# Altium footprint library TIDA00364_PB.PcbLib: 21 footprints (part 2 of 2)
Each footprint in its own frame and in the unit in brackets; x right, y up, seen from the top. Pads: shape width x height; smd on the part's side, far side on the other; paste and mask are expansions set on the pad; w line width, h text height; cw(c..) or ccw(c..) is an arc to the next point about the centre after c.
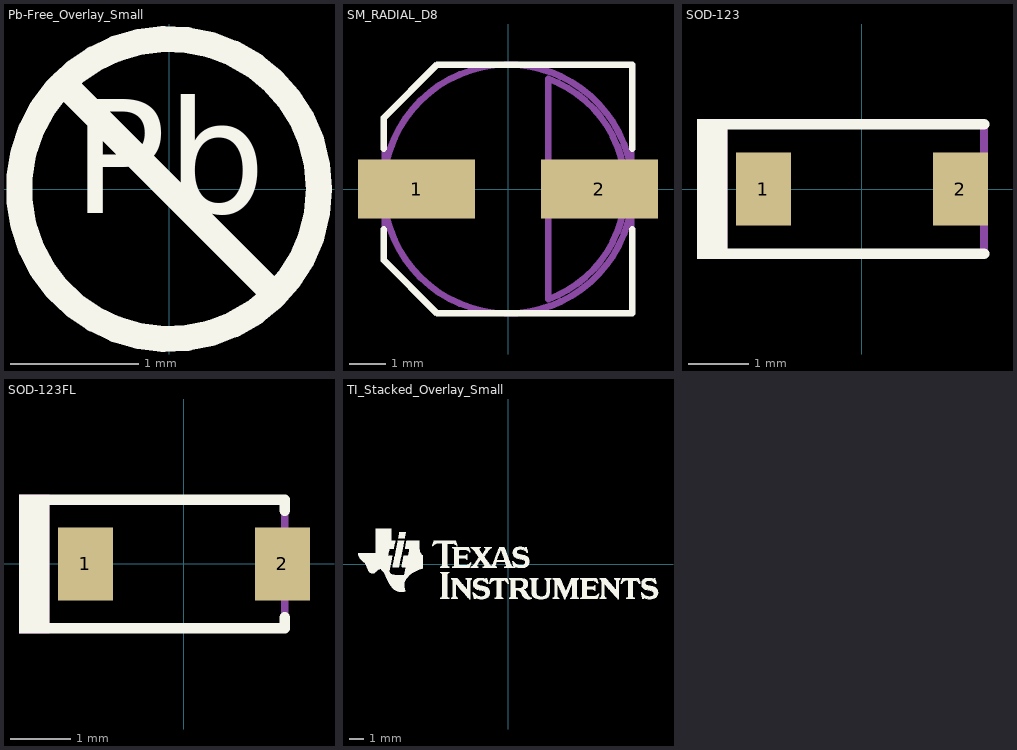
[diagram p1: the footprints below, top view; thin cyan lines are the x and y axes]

## Pb-Free_Overlay_Small [mm]
height 1.35
Top Overlay:
  circle w0.203: c0,0 r1.168
  lines w0.203: -0.826,0.826 0.826,-0.826
  text "Pb" at -0.752,-0.48 h1.52

## SM_RADIAL_D8 [mm] "6.3 x 7.7mm:  Panasonic D8"
height 8
pads (2):
  rect 3.2x1.6 smd: 1(-2.5,0) 2(2.5,0)
Top Overlay:
  lines w0.178: -3.398,-1.099 -3.398,-1.942 -1.94,-3.4 3.4,-3.4 3.4,-1.1 ; -3.398,1.099 -3.398,1.942 -1.94,3.4 3.4,3.4 3.4,1.1
Mechanical 5:
  lines w0.127: -3.398,-1.942 -1.94,-3.4 3.4,-3.4 3.4,3.4 -1.94,3.4 -3.398,1.942 -3.398,-1.942
  text ".Designator" at 0.762,0.889 h0.76
Mechanical 13:
  circle w0.178: c0,0 r3.4
  lines w0.178: 1.097,-3.014 ccw(c0,0) 1.097,3.014 1.097,-3.014
3D body: height 0.6, standoff 0, extent -3.398,-3.401 3.401,3.401
3D body: height 8.01, standoff 7.9, extent 1.097,-3.015 3.208,3.015
3D body: height 8, standoff 0.6, extent -3.399,-3.399 3.399,3.399

## SOD-123 [mm] "On Semi recommended land pattern"
height 1.35
pads (2):
  rect 0.915x1.22 smd: 1(-1.637,0) 2(1.637,0)
Top Overlay:
  rectangle: -2.743,-1.168 -2.235,1.168
  lines w0.178: -2.413,-1.079 2.032,-1.079 ; -2.413,1.079 2.032,1.079
Mechanical 5:
  rectangle: -2.743,-1.168 -2.235,1.168
  lines w0.127: -2.413,-1.079 2.032,-1.079 2.032,1.079 -2.413,1.079
  text ".Designator" at -1.956,-0.33 h0.76
3D body "SOD-123.stp": height 1.35, standoff 0, extent -1.932,-0.9 1.932,0.9

## SOD-123FL [mm] "Copied from SOD-123"
height 0.991
pads (2):
  rect 0.915x1.22 smd: 1(-1.637,0) 2(1.637,0)
Top Overlay:
  rectangle: -2.741,-1.156 -2.233,1.156
  lines w0.178: -2.438,-1.067 1.676,-1.067 1.676,-0.889 ; -2.438,1.067 1.676,1.067 1.676,0.889
Mechanical 5:
  rectangle: -2.741,-1.156 -2.233,1.156
  lines w0.127: -2.438,-1.067 1.676,-1.067 1.676,1.067 -2.438,1.067
  text ".Designator" at 0.635,0.381 h0.76
3D body "SOD-123FL.stp": height 1, standoff 0, extent -1.9,-0.9 1.9,0.9

## TI_Stacked_Overlay_Small [mm]
height 1.35
Top Overlay:
  drawing of 18 lines, arcs and shapes, not listed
